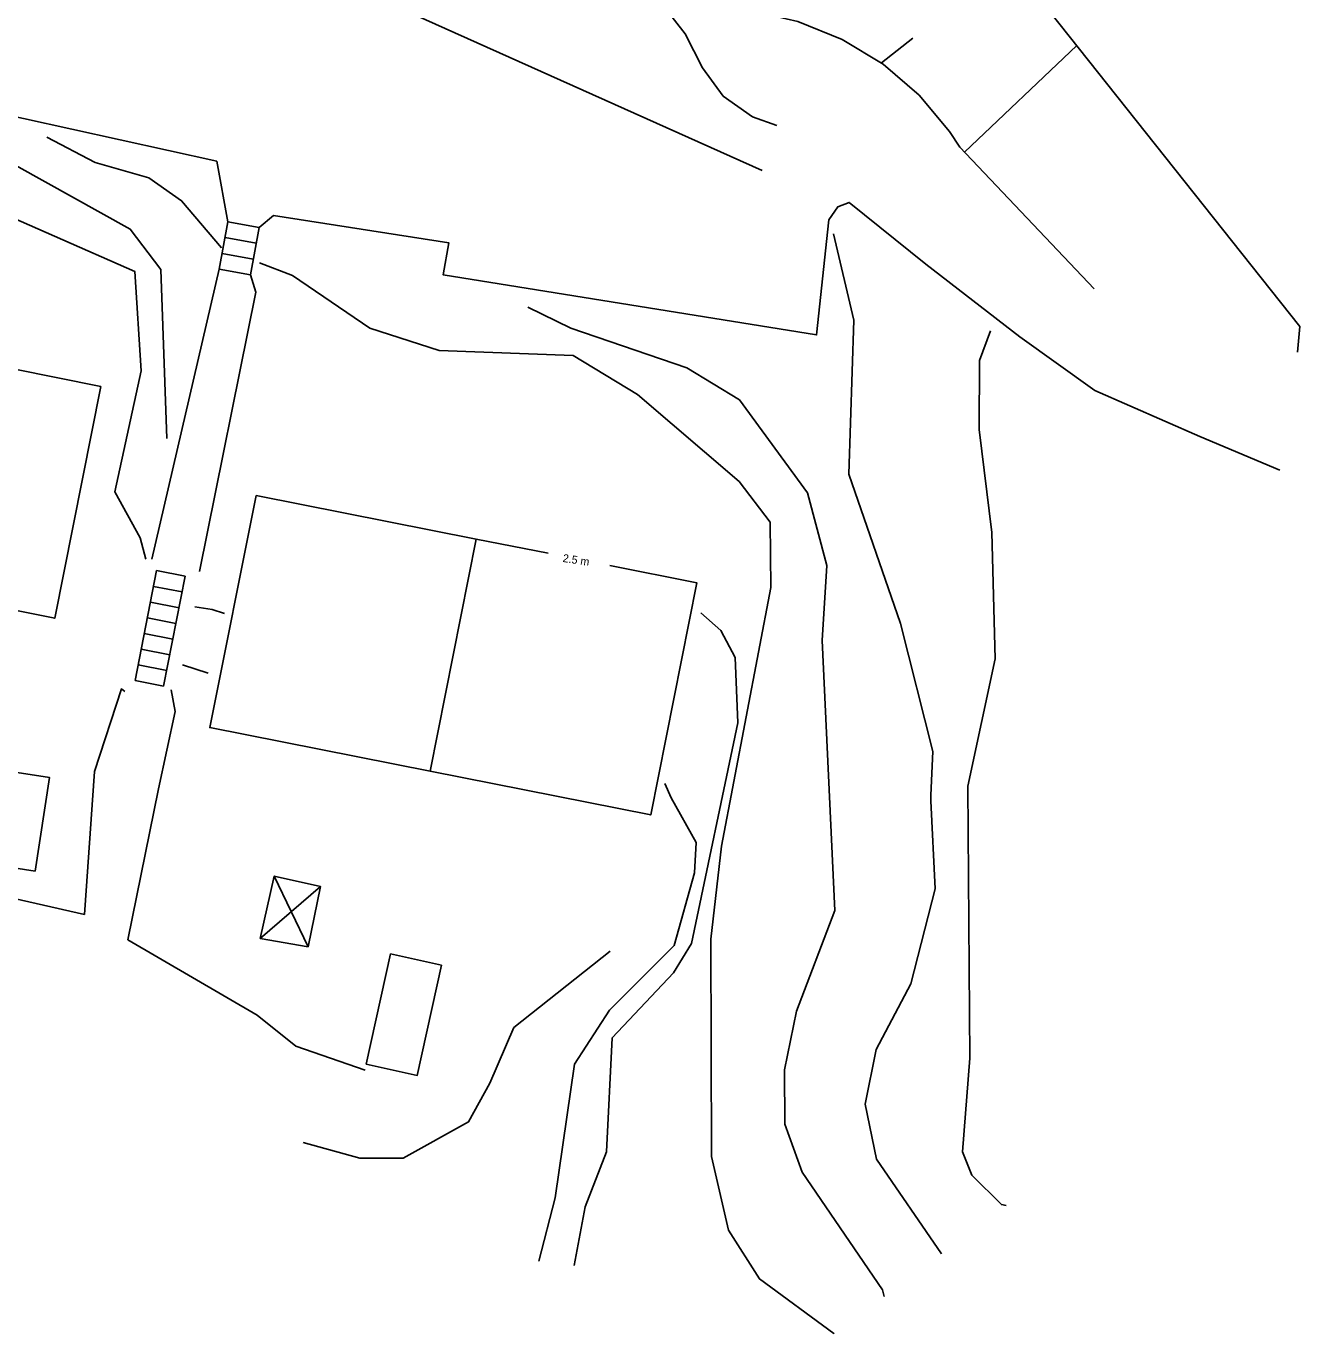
# Model space of a CAD drawing. Extents: x 1517610 to 1517815, y 6495294 to 6495395.
# Drawn here: x 1517766.92 to 1517814.66, y 6495298.64 to 6495347.65 of the extents above; entities that cross this region are included whole.
import ezdxf

# ---------------------------------------------------------------- set-up
doc = ezdxf.new("R2010")
doc.units = 0
for name, color, linetype in [('Baskarta', 7, 'Continuous'), ('Instruktioner', 7, 'Continuous'), ('Lager 1', 7, 'Continuous')]:
    doc.layers.add(name, color=color, linetype=linetype)

msp = doc.modelspace()

# ---------------------------------------------------------------- linework, layer by layer
at = {"layer": 'Baskarta'}
for points in [[(1517792.273, 6495363.476), (1517804.568, 6495349.106), (1517814.658, 6495336.399), (1517814.572, 6495335.438)], [(1517767.991, 6495353.384), (1517769.203, 6495353.189), (1517769.989, 6495353.325), (1517771.313, 6495353.554), (1517772.695, 6495354.096), (1517774.221, 6495354.186), (1517775.34, 6495353.763), (1517776.262, 6495352.992), (1517778.115, 6495351.443), (1517779.973, 6495350.174), (1517781.197, 6495349.827), (1517783.525, 6495349.373), (1517786.942, 6495349.171), (1517788.318, 6495349.436), (1517789.179, 6495349.352), (1517790.017, 6495349.016), (1517790.82, 6495348.385), (1517791.623, 6495347.36), (1517792.273, 6495346.09), (1517793.044, 6495345.032), (1517794.148, 6495344.246), (1517795.054, 6495343.928)], [(1517794.097, 6495348.22), (1517795.84, 6495347.828), (1517797.503, 6495347.155), (1517799.037, 6495346.222), (1517800.393, 6495345.059), (1517801.533, 6495343.7), (1517801.92, 6495343.109), (1517806.949, 6495337.807)], [(1517798.98, 6495346.271), (1517800.148, 6495347.194)], [(1517802.091, 6495342.929), (1517806.297, 6495346.928)], [(1517774.484, 6495340.316), (1517774.064, 6495342.586), (1517763.188, 6495344.992)], [(1517767.694, 6495343.487), (1517769.508, 6495342.543), (1517771.517, 6495341.967), (1517772.743, 6495341.108), (1517774.245, 6495339.344)], [(1517766.539, 6495342.424), (1517770.822, 6495340.044), (1517771.965, 6495338.529), (1517772.189, 6495332.193)], [(1517764.963, 6495341.101), (1517770.988, 6495338.458), (1517771.226, 6495334.732), (1517770.245, 6495330.192), (1517771.193, 6495328.474), (1517771.411, 6495327.678)], [(1517775.651, 6495340.102), (1517776.188, 6495340.549), (1517782.766, 6495339.526), (1517782.552, 6495338.327), (1517796.545, 6495336.078), (1517797.009, 6495340.387), (1517797.34, 6495340.876), (1517797.771, 6495341.044), (1517800.644, 6495338.734), (1517804.165, 6495336.001), (1517806.969, 6495333.992), (1517810.905, 6495332.268), (1517813.903, 6495331.004)], [(1517774.484, 6495340.316), (1517774.16, 6495338.546)], [(1517774.484, 6495340.316), (1517775.651, 6495340.102)], [(1517774.376, 6495339.726), (1517775.543, 6495339.512)], [(1517775.327, 6495338.332), (1517775.651, 6495340.102)], [(1517797.174, 6495339.863), (1517797.942, 6495336.628), (1517797.76, 6495330.863), (1517799.687, 6495325.262), (1517800.902, 6495320.466), (1517800.825, 6495318.826)], [(1517774.268, 6495339.136), (1517775.435, 6495338.922)], [(1517775.667, 6495338.782), (1517776.902, 6495338.307), (1517779.803, 6495336.333), (1517782.404, 6495335.491), (1517787.42, 6495335.308), (1517789.836, 6495333.849), (1517793.643, 6495330.579), (1517794.801, 6495329.056), (1517794.826, 6495326.611), (1517792.983, 6495316.914), (1517792.587, 6495313.429), (1517792.602, 6495305.288), (1517793.238, 6495302.531), (1517794.411, 6495300.696), (1517797.194, 6495298.651), (1517797.198, 6495298.64)], [(1517771.627, 6495327.673), (1517774.16, 6495338.546)], [(1517773.417, 6495327.207), (1517775.529, 6495337.681), (1517775.327, 6495338.332)], [(1517774.16, 6495338.546), (1517775.327, 6495338.332)], [(1517785.724, 6495337.118), (1517787.341, 6495336.331), (1517791.687, 6495334.85), (1517793.656, 6495333.641), (1517796.206, 6495330.159), (1517796.927, 6495327.432), (1517796.749, 6495324.627), (1517797.227, 6495314.51), (1517795.794, 6495310.728), (1517795.342, 6495308.541), (1517795.351, 6495306.501), (1517796.002, 6495304.697), (1517799.014, 6495300.293), (1517799.084, 6495300.045)], [(1517803.06, 6495336.234), (1517802.654, 6495335.125), (1517802.633, 6495332.531), (1517803.114, 6495328.672), (1517803.243, 6495323.937), (1517802.215, 6495319.171), (1517802.287, 6495308.967), (1517802.016, 6495305.467), (1517802.369, 6495304.585), (1517803.471, 6495303.484), (1517803.656, 6495303.45)], [(1517786.484, 6495327.894), (1517783.786, 6495328.428), (1517782.063, 6495319.727), (1517790.333, 6495318.089), (1517792.057, 6495326.791), (1517788.797, 6495327.436)], [(1517771.001, 6495323.121), (1517771.81, 6495327.243)], [(1517771.81, 6495327.243), (1517772.882, 6495327.033)], [(1517772.882, 6495327.033), (1517772.072, 6495322.911)], [(1517771.694, 6495326.654), (1517772.766, 6495326.444)], [(1517771.579, 6495326.066), (1517772.651, 6495325.855)], [(1517773.242, 6495325.89), (1517773.898, 6495325.789), (1517774.359, 6495325.633)], [(1517792.202, 6495325.663), (1517792.96, 6495324.999), (1517793.493, 6495323.984), (1517793.596, 6495321.539), (1517791.861, 6495313.272), (1517791.182, 6495312.169), (1517788.881, 6495309.73), (1517788.673, 6495305.464), (1517787.878, 6495303.402), (1517787.458, 6495301.205)], [(1517771.463, 6495325.477), (1517772.534, 6495325.266)], [(1517771.348, 6495324.888), (1517772.419, 6495324.677)], [(1517771.232, 6495324.299), (1517772.303, 6495324.088)], [(1517771.117, 6495323.71), (1517772.188, 6495323.5)], [(1517772.775, 6495323.71), (1517773.744, 6495323.398)], [(1517771.001, 6495323.121), (1517772.072, 6495322.911)], [(1517731.214, 6495301.803), (1517735.236, 6495320.103), (1517738.086, 6495319.25), (1517740.808, 6495317.471), (1517745.558, 6495316.191), (1517748.331, 6495315.638), (1517751.732, 6495316.033), (1517757.783, 6495316.926), (1517769.105, 6495314.362), (1517769.487, 6495319.714), (1517770.49, 6495322.814), (1517770.616, 6495322.713)], [(1517770.729, 6495313.41), (1517771.881, 6495319.062), (1517772.5, 6495321.959), (1517772.352, 6495322.78)], [(1517790.864, 6495319.271), (1517791.091, 6495318.724), (1517792.03, 6495317.061), (1517791.968, 6495315.913), (1517791.213, 6495313.201), (1517788.778, 6495310.769), (1517787.466, 6495308.744), (1517786.753, 6495303.744), (1517786.138, 6495301.361)], [(1517800.825, 6495318.826), (1517800.826, 6495318.623)], [(1517800.826, 6495318.623), (1517800.985, 6495315.318), (1517800.074, 6495311.763), (1517798.779, 6495309.293), (1517798.367, 6495307.253), (1517798.79, 6495305.191), (1517801.226, 6495301.64)], [(1517777.484, 6495313.144), (1517776.221, 6495315.795)], [(1517775.696, 6495313.458), (1517777.949, 6495315.412)], [(1517770.729, 6495313.41), (1517775.576, 6495310.579), (1517777.024, 6495309.427), (1517779.623, 6495308.523)], [(1517777.305, 6495305.815), (1517779.424, 6495305.223), (1517781.049, 6495305.224), (1517783.5, 6495306.585), (1517784.303, 6495308.032), (1517785.2, 6495310.117), (1517788.815, 6495312.98)]]:
    msp.add_lwpolyline(points, dxfattribs=at)
for points in [[(1517769.718, 6495334.144), (1517761.467, 6495335.803), (1517759.724, 6495327.112), (1517767.99, 6495325.461)], [(1517777.484, 6495313.144), (1517777.949, 6495315.412), (1517776.221, 6495315.795), (1517775.696, 6495313.458)], [(1517782.493, 6495312.458), (1517780.581, 6495312.882), (1517779.667, 6495308.748), (1517781.579, 6495308.324)]]:
    msp.add_lwpolyline(points, close=True, dxfattribs=at)
at = {"layer": 'Lager 1'}
msp.add_lwpolyline([(1517732.113, 6495362.471), (1517741.067, 6495358.236), (1517744.119, 6495356.666), (1517760.215, 6495354.578), (1517769.216, 6495351.591), (1517781.069, 6495348.264), (1517794.504, 6495342.235)], dxfattribs=at)
for points in [[(1517783.786, 6495328.428), (1517775.545, 6495330.058), (1517773.802, 6495321.364), (1517782.063, 6495319.727)], [(1517767.256, 6495315.984), (1517767.799, 6495319.489), (1517760.914, 6495320.554), (1517760.372, 6495317.05)]]:
    msp.add_lwpolyline(points, close=True, dxfattribs=at)

# ---------------------------------------------------------------- texts
at = {"layer": 'Instruktioner'}
msp.add_text('2.5 m', height=0.3, rotation=351.2925, dxfattribs=at).set_placement((1517787.015, 6495327.573))

doc.saveas('drawing.dxf')
